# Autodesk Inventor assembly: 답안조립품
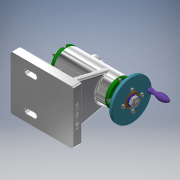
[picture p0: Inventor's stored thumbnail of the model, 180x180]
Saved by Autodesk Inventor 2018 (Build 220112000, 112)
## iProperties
Created: 2022-06
Part Number: 답안조립품
Material: 일반
Document SubType Name: Assembly
Designer: 4강의실
Author: 4강의실
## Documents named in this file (18)
- C:\Users\kimgi\Desktop\720606V1020\답안조립품.iam
- C:\Users\kimgi\Desktop\720606V1020\본체.ipt
- C:\Users\kimgi\Desktop\720606V1020\커버.ipt
- C:\Users\kimgi\Desktop\720606V1020\볼트 M3.ipt
- C:\Users\kimgi\Desktop\720606V1020\부시.ipt
- C:\Users\kimgi\Desktop\720606V1020\플랜지.ipt
- C:\Users\kimgi\Desktop\720606V1020\돌림판.ipt
- C:\Users\kimgi\Desktop\720606V1020\핸들.ipt
- C:\Users\kimgi\Desktop\720606V1020\나사축.ipt
- C:\Users\kimgi\Desktop\720606V1020\키 4 x 4 x 10.ipt
- C:\Users\kimgi\Desktop\720606V1020\중공축.ipt
- C:\Users\kimgi\Desktop\720606V1020\슬리브.ipt
- C:\Users\kimgi\Desktop\720606V1020\와셔.ipt
- C:\Users\kimgi\Desktop\720606V1020\너트 M8.ipt
- C:\Users\kimgi\Desktop\720606V1020\나사.ipt
- C:\Users\kimgi\Desktop\720606V1020\센터홀더.ipt
- C:\Users\kimgi\Desktop\720606V1020\센터.ipt
- C:\Users\kimgi\Desktop\720606V1020\멈춤나사 M3.ipt
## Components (2 placed, 2 different names)
1. 플랜지:1
2. 핸들:1
